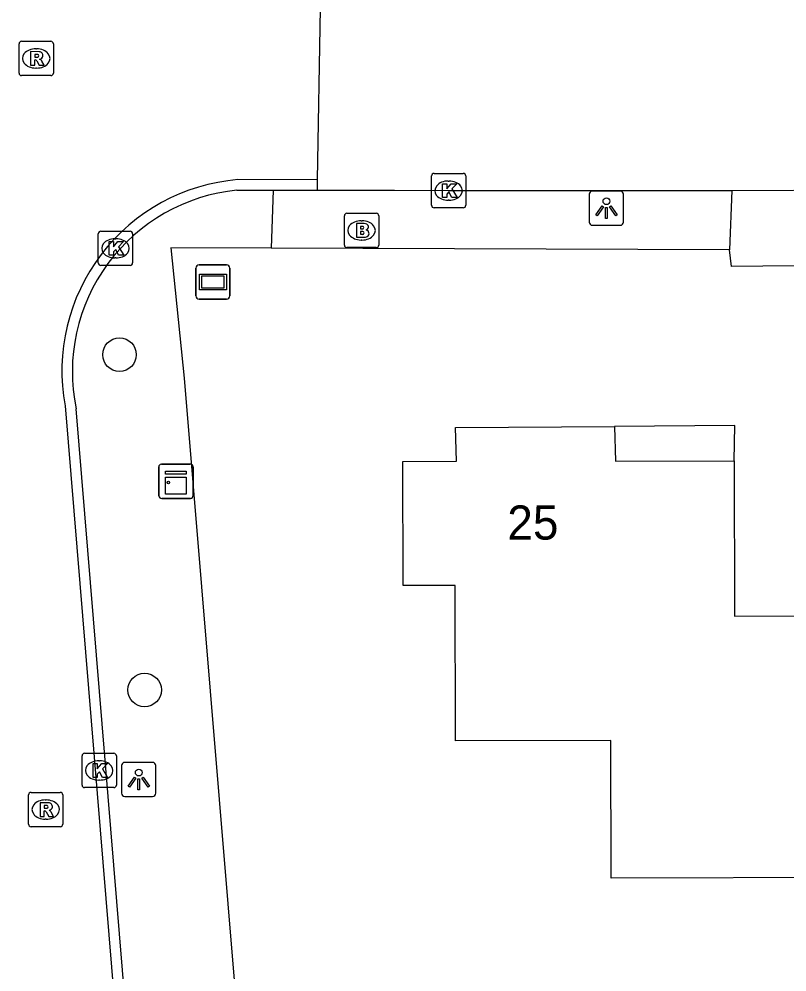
# Model space of a CAD drawing. Extents: x 162675 to 163482, y 379761 to 381227.
# Drawn here: x 163098.97 to 163121.35, y 380809.71 to 380837.48 of the extents above; entities that cross this region are included whole.
import ezdxf

# ---------------------------------------------------------------- set-up
doc = ezdxf.new("R2010")
doc.units = 0
for name, color, linetype in [('IMGEO_Boom', 7, 'Continuous'), ('IMGEO_Brandkraan', 7, 'Continuous'), ('IMGEO_Groenvoorziening', 7, 'Continuous'), ('IMGEO_Kast', 7, 'Continuous'), ('IMGEO_Kolk', 7, 'Continuous'), ('IMGEO_Lichtpunt', 7, 'Continuous'), ('IMGEO_Pand', 7, 'Continuous'), ('IMGEO_Pand_nummerreeks', 7, 'Continuous'), ('IMGEO_Pand_overbouw', 7, 'Continuous'), ('IMGEO_Parkeervlak_halfverhard', 7, 'Continuous'), ('IMGEO_Rijbaan_lokaal_gesloten', 7, 'Continuous'), ('IMGEO_Rijbaan_lokaal_open', 7, 'Continuous'), ('IMGEO_Rioolput', 7, 'Continuous'), ('IMGEO_Verklikker', 7, 'Continuous'), ('IMGEO_Voetpad_open', 7, 'Continuous')]:
    doc.layers.add(name, color=color, linetype=linetype)

msp = doc.modelspace()

# ---------------------------------------------------------------- linework, layer by layer
at = {"layer": 'IMGEO_Boom'}
for centre in [(163101.899, 380827.697), (163102.63, 380817.927)]:
    msp.add_circle(centre, 0.489, dxfattribs=at)
at = {"layer": 'IMGEO_Brandkraan'}
for p, q in [((163108.452, 380830.893), (163108.452, 380831.745)), ((163108.527, 380831.819), (163109.379, 380831.819)), ((163109.453, 380831.745), (163109.453, 380830.893)), ((163108.94, 380831.599), (163108.965, 380831.599)), ((163109.379, 380830.819), (163108.527, 380830.819)), ((163108.963, 380831.039), (163108.938, 380831.039))]:
    msp.add_line(p, q, dxfattribs=at)
for points in [[(163108.452, 380830.893), (163108.452, 380831.745)], [(163108.527, 380831.819), (163109.379, 380831.819)], [(163109.453, 380831.745), (163109.453, 380830.893)], [(163108.8, 380831.519), (163108.8, 380831.119), (163109.013, 380831.119)], [(163109.031, 380831.519), (163108.8, 380831.519)], [(163108.979, 380831.438), (163108.925, 380831.438), (163108.925, 380831.362)], [(163108.925, 380831.362), (163108.978, 380831.362)], [(163108.987, 380831.286), (163108.925, 380831.286), (163108.925, 380831.205)], [(163108.925, 380831.205), (163108.987, 380831.205)], [(163109.379, 380830.819), (163108.527, 380830.819)]]:
    msp.add_lwpolyline(points, dxfattribs=at)
for centre, radius, start, end in [((163108.529, 380831.743), 0.0765, 91.552, 178.448), ((163108.529, 380831.743), 0.0765, 91.552, 178.448), ((163109.377, 380831.743), 0.0765, 1.552, 88.448), ((163109.377, 380831.743), 0.0765, 1.552, 88.448), ((163108.98, 380831.4), 0.0379, 267.8285, 90.9355), ((163109.035, 380831.374), 0.145, 59.4692, 91.5367), ((163109.06, 380831.421), 0.0922, 285.5137, 58.1501), ((163108.988, 380831.245), 0.0404, 269.8759, 90.5077), ((163109.019, 380831.37), 0.251, 268.6676, 293.5347), ((163109.065, 380831.229), 0.105, 301.3115, 78.989), ((163108.529, 380830.895), 0.0765, 181.552, 268.448), ((163108.529, 380830.895), 0.0765, 181.552, 268.448), ((163109.377, 380830.895), 0.0765, 271.552, 358.448), ((163109.377, 380830.895), 0.0765, 271.552, 358.448)]:
    msp.add_arc(centre, radius, start, end, dxfattribs=at)
for centre, major_axis, ratio, start_param, end_param in [((163108.939, 380831.319), (-0.387, 0.002), 0.722429, 4.712389, 7.853982), ((163108.964, 380831.319), (-0.39, 0.002), 0.717154, 1.570796, 4.712389)]:
    msp.add_ellipse(centre, major_axis=major_axis, ratio=ratio, start_param=start_param, end_param=end_param, dxfattribs=at)
at = {"layer": 'IMGEO_Groenvoorziening'}
msp.add_lwpolyline([(163106.322, 380830.801), (163103.397, 380830.811), (163103.788, 380827.01), (163107.334, 380784.216), (163107.736, 380779.339), (163120.148, 380780.444), (163121.048, 380780.505)], dxfattribs=at)
at = {"layer": 'IMGEO_Kast'}
for p, q in [((163103.044, 380823.584), (163103.044, 380824.425)), ((163103.044, 380824.425), (163103.044, 380823.584)), ((163103.119, 380824.509), (163103.96, 380824.509)), ((163103.96, 380824.509), (163103.119, 380824.509)), ((163104.044, 380824.434), (163104.044, 380823.593)), ((163104.044, 380823.593), (163104.044, 380824.434)), ((163103.969, 380823.509), (163103.128, 380823.509)), ((163103.128, 380823.509), (163103.969, 380823.509))]:
    msp.add_line(p, q, dxfattribs=at)
for points in [[(163103.239, 380824.299), (163103.839, 380824.299), (163103.839, 380824.214), (163103.239, 380824.214), (163103.239, 380824.299)], [(163103.239, 380824.124), (163103.839, 380824.124), (163103.839, 380823.635), (163103.239, 380823.635), (163103.239, 380824.124)]]:
    msp.add_lwpolyline(points, dxfattribs=at)
msp.add_circle((163103.323, 380823.973), 0.0377, dxfattribs=at)
for centre, start, end in [((163103.122, 380824.431), 92.4484, 184.2845), ((163103.122, 380824.431), 92.4484, 184.2845), ((163103.966, 380824.431), 2.4484, 94.2845), ((163103.966, 380824.431), 2.4484, 94.2845), ((163103.122, 380823.587), 182.4484, 274.2845), ((163103.122, 380823.587), 182.4484, 274.2845), ((163103.966, 380823.587), 272.4484, 4.2845), ((163103.966, 380823.587), 272.4484, 4.2845)]:
    msp.add_arc(centre, 0.0779, start, end, dxfattribs=at)
at = {"layer": 'IMGEO_Kolk'}
for p, q in [((163110.989, 380832.053), (163110.989, 380832.905)), ((163111.064, 380832.979), (163111.916, 380832.979)), ((163111.477, 380832.759), (163111.502, 380832.759)), ((163111.99, 380832.905), (163111.99, 380832.053)), ((163111.5, 380832.199), (163111.475, 380832.199)), ((163111.916, 380831.979), (163111.064, 380831.979)), ((163101.281, 380830.37), (163101.281, 380831.222)), ((163101.356, 380831.296), (163102.208, 380831.296)), ((163101.769, 380831.076), (163101.794, 380831.076)), ((163102.282, 380831.222), (163102.282, 380830.37)), ((163101.792, 380830.516), (163101.767, 380830.516)), ((163102.208, 380830.296), (163101.356, 380830.296)), ((163100.882, 380816.081), (163101.734, 380816.081)), ((163100.807, 380815.155), (163100.807, 380816.007)), ((163101.295, 380815.861), (163101.32, 380815.861)), ((163101.808, 380816.007), (163101.808, 380815.155)), ((163101.318, 380815.301), (163101.293, 380815.301)), ((163101.734, 380815.081), (163100.882, 380815.081))]:
    msp.add_line(p, q, dxfattribs=at)
for points in [[(163110.989, 380832.053), (163110.989, 380832.905)], [(163111.064, 380832.979), (163111.916, 380832.979)], [(163111.99, 380832.905), (163111.99, 380832.053)], [(163111.31, 380832.679), (163111.433, 380832.679), (163111.433, 380832.528), (163111.563, 380832.679), (163111.727, 380832.679), (163111.581, 380832.528), (163111.734, 380832.279), (163111.582, 380832.279), (163111.497, 380832.443), (163111.433, 380832.376), (163111.433, 380832.279), (163111.31, 380832.279), (163111.31, 380832.679)], [(163111.916, 380831.979), (163111.064, 380831.979)], [(163101.281, 380830.37), (163101.281, 380831.222)], [(163101.356, 380831.296), (163102.208, 380831.296)], [(163102.282, 380831.222), (163102.282, 380830.37)], [(163101.602, 380830.996), (163101.725, 380830.996), (163101.725, 380830.845), (163101.855, 380830.996), (163102.019, 380830.996), (163101.873, 380830.845), (163102.026, 380830.596), (163101.874, 380830.596), (163101.789, 380830.76), (163101.725, 380830.693), (163101.725, 380830.596), (163101.602, 380830.596), (163101.602, 380830.996)], [(163102.208, 380830.296), (163101.356, 380830.296)], [(163100.882, 380816.081), (163101.734, 380816.081)], [(163100.807, 380815.155), (163100.807, 380816.007)], [(163101.808, 380816.007), (163101.808, 380815.155)], [(163101.128, 380815.781), (163101.251, 380815.781), (163101.251, 380815.63), (163101.381, 380815.781), (163101.545, 380815.781), (163101.399, 380815.63), (163101.552, 380815.381), (163101.4, 380815.381), (163101.315, 380815.545), (163101.251, 380815.478), (163101.251, 380815.381), (163101.128, 380815.381), (163101.128, 380815.781)], [(163101.734, 380815.081), (163100.882, 380815.081)]]:
    msp.add_lwpolyline(points, dxfattribs=at)
for centre, start, end in [((163111.066, 380832.903), 91.552, 178.448), ((163111.066, 380832.903), 91.552, 178.448), ((163111.914, 380832.903), 1.552, 88.448), ((163111.914, 380832.903), 1.552, 88.448), ((163111.066, 380832.055), 181.552, 268.448), ((163111.066, 380832.055), 181.552, 268.448), ((163111.914, 380832.055), 271.552, 358.448), ((163111.914, 380832.055), 271.552, 358.448), ((163101.358, 380831.22), 91.552, 178.448), ((163101.358, 380831.22), 91.552, 178.448), ((163102.206, 380831.22), 1.552, 88.448), ((163102.206, 380831.22), 1.552, 88.448), ((163101.358, 380830.372), 181.552, 268.448), ((163101.358, 380830.372), 181.552, 268.448), ((163102.206, 380830.372), 271.552, 358.448), ((163102.206, 380830.372), 271.552, 358.448), ((163100.884, 380816.005), 91.552, 178.448), ((163100.884, 380816.005), 91.552, 178.448), ((163101.732, 380816.005), 1.552, 88.448), ((163101.732, 380816.005), 1.552, 88.448), ((163100.884, 380815.157), 181.552, 268.448), ((163100.884, 380815.157), 181.552, 268.448), ((163101.732, 380815.157), 271.552, 358.448), ((163101.732, 380815.157), 271.552, 358.448)]:
    msp.add_arc(centre, 0.0765, start, end, dxfattribs=at)
for centre, major_axis, ratio, start_param, end_param in [((163111.476, 380832.479), (-0.387, 0.002), 0.722429, 4.712389, 7.853982), ((163111.501, 380832.479), (-0.39, 0.002), 0.717154, 1.570796, 4.712389), ((163101.768, 380830.796), (-0.387, 0.002), 0.722429, 4.712389, 7.853982), ((163101.793, 380830.796), (-0.39, 0.002), 0.717154, 1.570796, 4.712389), ((163101.294, 380815.581), (-0.387, 0.002), 0.722429, 4.712389, 7.853982), ((163101.319, 380815.581), (-0.39, 0.002), 0.717154, 1.570796, 4.712389)]:
    msp.add_ellipse(centre, major_axis=major_axis, ratio=ratio, start_param=start_param, end_param=end_param, dxfattribs=at)
at = {"layer": 'IMGEO_Lichtpunt'}
for p, q in [((163116.49, 380832.466), (163115.682, 380832.466)), ((163116.49, 380832.466), (163115.682, 380832.466)), ((163115.588, 380832.371), (163115.588, 380831.564)), ((163115.588, 380832.371), (163115.588, 380831.564)), ((163116.584, 380831.564), (163116.584, 380832.371)), ((163116.584, 380831.564), (163116.584, 380832.371)), ((163115.682, 380831.47), (163116.49, 380831.47)), ((163115.682, 380831.47), (163116.49, 380831.47)), ((163102.863, 380815.817), (163102.055, 380815.817)), ((163102.863, 380815.817), (163102.055, 380815.817)), ((163101.961, 380815.722), (163101.961, 380814.915)), ((163101.961, 380815.722), (163101.961, 380814.915)), ((163102.957, 380814.915), (163102.957, 380815.722)), ((163102.957, 380814.915), (163102.957, 380815.722)), ((163102.055, 380814.821), (163102.863, 380814.821)), ((163102.055, 380814.821), (163102.863, 380814.821))]:
    msp.add_line(p, q, dxfattribs=at)
for points in [[(163115.962, 380832.035), (163116.001, 380832.007), (163115.813, 380831.745), (163115.775, 380831.772), (163115.962, 380832.035)], [(163116.064, 380831.987), (163116.111, 380831.987), (163116.111, 380831.665), (163116.064, 380831.665), (163116.064, 380831.987)], [(163116.174, 380832.007), (163116.212, 380832.034), (163116.399, 380831.772), (163116.36, 380831.744), (163116.174, 380832.007)], [(163102.335, 380815.386), (163102.374, 380815.358), (163102.186, 380815.096), (163102.148, 380815.123), (163102.335, 380815.386)], [(163102.437, 380815.338), (163102.484, 380815.338), (163102.484, 380815.016), (163102.437, 380815.016), (163102.437, 380815.338)], [(163102.547, 380815.358), (163102.585, 380815.385), (163102.772, 380815.123), (163102.733, 380815.095), (163102.547, 380815.358)]]:
    msp.add_lwpolyline(points, dxfattribs=at)
for centre in [(163116.087, 380832.169), (163102.46, 380815.52)]:
    msp.add_circle(centre, 0.0994, dxfattribs=at)
for centre, start, end in [((163115.682, 380832.371), 90, 180), ((163115.682, 380832.371), 90, 180), ((163116.49, 380832.371), 0, 90), ((163116.49, 380832.371), 0, 90), ((163115.682, 380831.564), 180, 270), ((163115.682, 380831.564), 180, 270), ((163116.49, 380831.564), 270, 0), ((163116.49, 380831.564), 270, 360), ((163102.055, 380815.722), 90, 180), ((163102.055, 380815.722), 90, 180), ((163102.863, 380815.722), 0, 90), ((163102.863, 380815.722), 0, 90), ((163102.055, 380814.915), 180, 270), ((163102.055, 380814.915), 180, 270), ((163102.863, 380814.915), 270, 0), ((163102.863, 380814.915), 270, 360)]:
    msp.add_arc(centre, 0.0946, start, end, dxfattribs=at)
at = {"layer": 'IMGEO_Pand'}
msp.add_lwpolyline([(163116.322, 380825.602), (163116.351, 380824.591), (163119.805, 380824.601), (163119.815, 380820.082), (163123.331, 380820.09), (163123.347, 380812.458), (163116.227, 380812.444), (163116.22, 380816.452), (163111.691, 380816.442), (163111.682, 380820.972), (163110.166, 380820.969), (163110.159, 380824.585), (163111.722, 380824.595), (163111.693, 380825.571), (163116.322, 380825.602)], dxfattribs=at)
at = {"layer": 'IMGEO_Pand_overbouw'}
msp.add_lwpolyline([(163116.322, 380825.602), (163116.351, 380824.591), (163119.805, 380824.601), (163119.828, 380825.631)], close=True, dxfattribs=at)
at = {"layer": 'IMGEO_Parkeervlak_halfverhard'}
for points in [[(163106.381, 380832.492), (163106.322, 380830.801)], [(163119.673, 380830.754), (163106.322, 380830.801)]]:
    msp.add_lwpolyline(points, dxfattribs=at)
at = {"layer": 'IMGEO_Rijbaan_lokaal_gesloten'}
for points in [[(163107.746, 380837.789), (163107.662, 380832.793)], [(163107.662, 380832.793), (163105.347, 380832.798)], [(163107.662, 380832.793), (163107.657, 380832.494)], [(163107.657, 380832.494), (163109.911, 380832.496), (163111.49, 380832.479), (163119.744, 380832.482)], [(163119.744, 380832.482), (163123.341, 380832.497)], [(163100.315, 380826.209), (163103.871, 380783.141)]]:
    msp.add_lwpolyline(points, dxfattribs=at)
msp.add_arc((163105.809, 380827.23), 5.588, 94.7387, 190.5236, dxfattribs=at)
at = {"layer": 'IMGEO_Rijbaan_lokaal_open'}
for points in [[(163105.321, 380832.491), (163106.381, 380832.492)], [(163106.381, 380832.492), (163107.657, 380832.494)], [(163104.182, 380783.167), (163100.635, 380826.124)]]:
    msp.add_lwpolyline(points, dxfattribs=at)
msp.add_arc((163105.843, 380827.199), 5.318, 95.6309, 191.6643, dxfattribs=at)
at = {"layer": 'IMGEO_Rioolput'}
for p, q in [((163098.972, 380835.904), (163098.972, 380836.756)), ((163099.047, 380836.83), (163099.899, 380836.83)), ((163099.973, 380836.756), (163099.973, 380835.904)), ((163099.46, 380836.61), (163099.485, 380836.61)), ((163099.899, 380835.83), (163099.047, 380835.83)), ((163099.483, 380836.05), (163099.458, 380836.05)), ((163099.247, 380814.016), (163099.247, 380814.868)), ((163099.322, 380814.942), (163100.174, 380814.942)), ((163099.735, 380814.722), (163099.76, 380814.722)), ((163100.248, 380814.868), (163100.248, 380814.016)), ((163099.758, 380814.162), (163099.733, 380814.162)), ((163100.174, 380813.942), (163099.322, 380813.942))]:
    msp.add_line(p, q, dxfattribs=at)
for points in [[(163098.972, 380835.904), (163098.972, 380836.756)], [(163099.047, 380836.83), (163099.899, 380836.83)], [(163099.973, 380836.756), (163099.973, 380835.904)], [(163099.561, 380836.528), (163099.309, 380836.53), (163099.309, 380836.13)], [(163099.487, 380836.449), (163099.433, 380836.449), (163099.433, 380836.368)], [(163099.433, 380836.368), (163099.485, 380836.368)], [(163099.309, 380836.13), (163099.433, 380836.13), (163099.433, 380836.292), (163099.444, 380836.292)], [(163099.491, 380836.263), (163099.562, 380836.13), (163099.702, 380836.13), (163099.637, 380836.256)], [(163099.899, 380835.83), (163099.047, 380835.83)], [(163099.247, 380814.016), (163099.247, 380814.868)], [(163099.322, 380814.942), (163100.174, 380814.942)], [(163100.248, 380814.868), (163100.248, 380814.016)], [(163099.836, 380814.64), (163099.584, 380814.642), (163099.584, 380814.242)], [(163099.584, 380814.242), (163099.708, 380814.242), (163099.708, 380814.404), (163099.719, 380814.404)], [(163099.762, 380814.561), (163099.708, 380814.561), (163099.708, 380814.48)], [(163099.708, 380814.48), (163099.76, 380814.48)], [(163099.766, 380814.375), (163099.837, 380814.242), (163099.977, 380814.242), (163099.912, 380814.368)], [(163100.174, 380813.942), (163099.322, 380813.942)]]:
    msp.add_lwpolyline(points, dxfattribs=at)
for centre, radius, start, end in [((163099.049, 380836.754), 0.0765, 91.552, 178.448), ((163099.049, 380836.754), 0.0765, 91.552, 178.448), ((163099.897, 380836.754), 0.0765, 1.552, 88.448), ((163099.897, 380836.754), 0.0765, 1.552, 88.448), ((163099.469, 380836.557), 0.19, 274.7715, 282.9687), ((163099.493, 380836.353), 0.0964, 77.0061, 93.1865), ((163099.507, 380836.41), 0.0378, 276.6634, 79.6772), ((163099.56, 380836.418), 0.109, 350.3612, 89.416), ((163099.558, 380836.418), 0.112, 277.5842, 350.9817), ((163099.443, 380836.239), 0.0533, 26.0293, 88.6989), ((163099.542, 380836.203), 0.108, 29.5134, 73.7905), ((163099.049, 380835.906), 0.0765, 181.552, 268.448), ((163099.049, 380835.906), 0.0765, 181.552, 268.448), ((163099.897, 380835.906), 0.0765, 271.552, 358.448), ((163099.897, 380835.906), 0.0765, 271.552, 358.448), ((163099.324, 380814.866), 0.0765, 91.552, 178.448), ((163099.324, 380814.866), 0.0765, 91.552, 178.448), ((163100.172, 380814.866), 0.0765, 1.552, 88.448), ((163100.172, 380814.866), 0.0765, 1.552, 88.448), ((163099.718, 380814.351), 0.0533, 26.0293, 88.6989), ((163099.744, 380814.669), 0.19, 274.7715, 282.9687), ((163099.768, 380814.465), 0.0964, 77.0061, 93.1865), ((163099.782, 380814.522), 0.0378, 276.6634, 79.6772), ((163099.835, 380814.53), 0.109, 350.3612, 89.416), ((163099.833, 380814.53), 0.112, 277.5842, 350.9817), ((163099.817, 380814.315), 0.108, 29.5134, 73.7905), ((163099.324, 380814.018), 0.0765, 181.552, 268.448), ((163099.324, 380814.018), 0.0765, 181.552, 268.448), ((163100.172, 380814.018), 0.0765, 271.552, 358.448), ((163100.172, 380814.018), 0.0765, 271.552, 358.448)]:
    msp.add_arc(centre, radius, start, end, dxfattribs=at)
for centre, major_axis, ratio, start_param, end_param in [((163099.459, 380836.33), (-0.387, 0.002), 0.722429, 4.712389, 7.853982), ((163099.484, 380836.33), (-0.39, 0.002), 0.717154, 1.570796, 4.712389), ((163099.734, 380814.442), (-0.387, 0.002), 0.722429, 4.712389, 7.853982), ((163099.759, 380814.442), (-0.39, 0.002), 0.717154, 1.570796, 4.712389)]:
    msp.add_ellipse(centre, major_axis=major_axis, ratio=ratio, start_param=start_param, end_param=end_param, dxfattribs=at)
at = {"layer": 'IMGEO_Verklikker'}
for p, q in [((163104.225, 380830.315), (163105.015, 380830.315)), ((163105.015, 380830.315), (163104.225, 380830.315)), ((163104.125, 380829.415), (163104.125, 380830.215)), ((163104.125, 380830.215), (163104.125, 380829.415)), ((163105.115, 380830.215), (163105.115, 380829.415)), ((163105.115, 380829.415), (163105.115, 380830.215)), ((163105.015, 380829.315), (163104.225, 380829.315)), ((163104.225, 380829.315), (163105.015, 380829.315))]:
    msp.add_line(p, q, dxfattribs=at)
for points in [[(163104.226, 380830.047), (163105.014, 380830.047), (163105.014, 380829.583), (163104.226, 380829.583), (163104.226, 380830.047)], [(163104.291, 380829.982), (163104.291, 380829.648), (163104.949, 380829.648), (163104.949, 380829.982), (163104.291, 380829.982)]]:
    msp.add_lwpolyline(points, dxfattribs=at)
for centre, start, end in [((163104.225, 380830.215), 90, 180), ((163104.225, 380830.215), 90, 180), ((163105.015, 380830.215), 0, 90), ((163105.015, 380830.215), 360, 90), ((163104.225, 380829.415), 180, 270), ((163104.225, 380829.415), 180, 270), ((163105.015, 380829.415), 270, 0), ((163105.015, 380829.415), 270, 0)]:
    msp.add_arc(centre, 0.1, start, end, dxfattribs=at)
at = {"layer": 'IMGEO_Voetpad_open'}
for points in [[(163119.744, 380832.482), (163119.673, 380830.754)], [(163123.374, 380830.767), (163123.388, 380830.302), (163119.732, 380830.269), (163119.673, 380830.754)]]:
    msp.add_lwpolyline(points, dxfattribs=at)

# ---------------------------------------------------------------- texts
at = {"layer": 'IMGEO_Pand_nummerreeks'}
msp.add_text('25', height=1, rotation=0.3899, dxfattribs=at).set_placement((163113.204, 380822.302))

doc.saveas('drawing.dxf')
